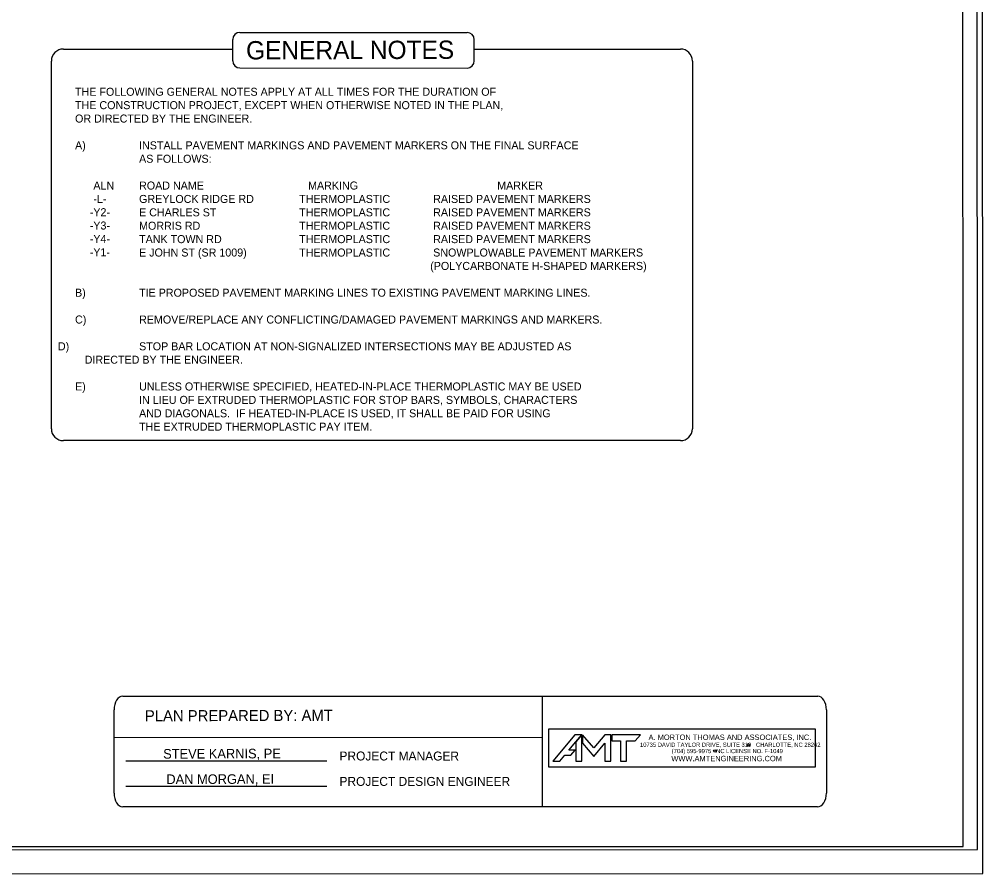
# Model space of a CAD drawing. Extents: x 2088685 to 2091711, y 751320 to 752417.
# Drawn here: x 2090071 to 2090874, y 751321 to 752034 of the extents above; entities that cross this region are included whole.
import ezdxf

# ---------------------------------------------------------------- set-up
doc = ezdxf.new("R2010")
doc.units = 0
for name, color, linetype in [('Default', 7, 'Continuous'), ('Prop Grid Mask', 7, 'Continuous'), ('Sheet Block Title CELL', 7, 'Continuous'), ('Sheet Plot Border Inside CELL', 7, 'Continuous'), ('Sheet Plot Border Outside CELL', 7, 'Continuous'), ('Sheet Title CELL', 7, 'Continuous')]:
    doc.layers.add(name, color=color, linetype=linetype)

msp = doc.modelspace()

# ---------------------------------------------------------------- linework, layer by layer
at = {"layer": 'Default'}
for p, q in [((2090157.69, 751469.16), (2090736.96, 751469.26)), ((2090507.46, 751376.87), (2090507.44, 751469.22)), ((2090150.52, 751388.35), (2090150.5, 751457.72)), ((2090744.15, 751457.77), (2090744.18, 751388.41)), ((2090150.49, 751434.81), (2090507.45, 751434.96)), ((2090160.34, 751415.41), (2090327.71, 751415.33)), ((2090160.33, 751394.22), (2090327.7, 751394.13)), ((2090736.86, 751376.91), (2090157.72, 751376.81))]:
    msp.add_line(p, q, dxfattribs=at)
for centre, major_axis, start_param, end_param in [((2090157.7, 751457.72), (0.01, 11.49), 0.000702, 1.571498), ((2090736.96, 751457.77), (0.01, 11.49), 4.713091, 6.283887), ((2090157.72, 751388.36), (-0.01, -11.49), 4.713091, 6.283887), ((2090736.98, 751388.4), (-0.01, -11.49), 6.268607, 7.854684)]:
    msp.add_ellipse(centre, major_axis=major_axis, ratio=0.62659, start_param=start_param, end_param=end_param, dxfattribs=at)
at = {"layer": 'Prop Grid Mask'}
msp.add_lwpolyline([(2090512.93, 751442.03), (2090734.97, 751442.03), (2090734.97, 751410.08), (2090512.93, 751410.08)], close=True, dxfattribs=at)
at = {"layer": 'Sheet Block Title CELL'}
for points in [[(2090858, 752393.6), (2089358.33, 752393.49), (2089358.41, 751343.72), (2090858.08, 751343.83)], [(2090512.93, 751442.03), (2090734.97, 751442.03), (2090734.97, 751410.08), (2090512.93, 751410.08)]]:
    msp.add_lwpolyline(points, close=True, dxfattribs=at)
for points in [[(2090535.36, 751431.17), (2090540.39, 751437.07), (2090534.51, 751437.07), (2090516.28, 751415.12), (2090521.98, 751415.12), (2090526.07, 751420.05), (2090531.29, 751420.05), (2090534.87, 751424.2), (2090529.48, 751424.2), (2090535.36, 751431.17)], [(2090540.39, 751415.12), (2090540.39, 751437.07), (2090535.36, 751431.17), (2090535.36, 751415.12), (2090540.39, 751415.12)], [(2090550.26, 751418.99), (2090559.59, 751430.1), (2090559.59, 751415.12), (2090564.62, 751415.12), (2090564.62, 751437.07), (2090559.59, 751437.07), (2090550.26, 751426.12), (2090541.04, 751437.07), (2090541.04, 751430.08), (2090550.26, 751418.99)], [(2090577.65, 751415.12), (2090577.65, 751432.04), (2090584.95, 751432.04), (2090589.15, 751437.07), (2090565.27, 751437.07), (2090565.27, 751432.04), (2090572.62, 751432.04), (2090572.62, 751415.12), (2090577.65, 751415.12)]]:
    msp.add_lwpolyline(points, dxfattribs=at)
for centre in [(2090679.16, 751428.6), (2090651.24, 751423.37)]:
    msp.add_circle(centre, 1, dxfattribs=at)
at = {"layer": 'Sheet Plot Border Inside CELL'}
msp.add_lwpolyline([(2090869.93, 752396.91), (2089204.86, 752396.79), (2089204.94, 751341.13), (2090870.01, 751341.25)], close=True, dxfattribs=at)
at = {"layer": 'Sheet Plot Border Outside CELL'}
msp.add_lwpolyline([(2090874.42, 752416.91), (2089191.88, 752416.79), (2089191.96, 751321.13), (2090874.5, 751321.25)], close=True, dxfattribs=at)
at = {"layer": 'Sheet Title CELL'}
for p, q in [((2090249.34, 751999.06), (2090249.35, 752016.69)), ((2090450.74, 751998.96), (2090450.74, 752016.59))]:
    msp.add_line(p, q, dxfattribs=at)
for points in [[(2090255.35, 752022.69), (2090444.75, 752022.6)], [(2090108.24, 752008.81), (2090249.34, 752008.81)], [(2090450.74, 752008.81), (2090622.48, 752008.81)], [(2090098.24, 751692.25), (2090098.24, 751998.81)], [(2090632.48, 751998.81), (2090632.48, 751692.25)], [(2090255.33, 751993.05), (2090444.73, 751992.97)], [(2090622.48, 751682.25), (2090108.24, 751682.25)]]:
    msp.add_lwpolyline(points, dxfattribs=at)
for centre, radius, start, end in [((2090255.35, 752016.69), 6, 89.97341, 179.97341), ((2090444.74, 752016.6), 6, 359.97341, 89.97341), ((2090108.24, 751998.81), 10, 90, 180), ((2090622.48, 751998.81), 10, 0, 90), ((2090255.34, 751999.05), 6, 179.97341, 269.97341), ((2090444.74, 751998.97), 6, 269.97341, 359.97341), ((2090108.24, 751692.25), 10, 180, 270), ((2090622.48, 751692.25), 10, 270, 0)]:
    msp.add_arc(centre, radius, start, end, dxfattribs=at)

# ---------------------------------------------------------------- texts
at = {"layer": 'Default'}
for s, height, rotation, p in [('GENERAL NOTES', 15.2572, 0.15565, (2090260.52, 752000.16)), ('ALN', 6.671, 359.97341, (2090133.24, 751891.66)), ('-L-', 6.671, 359.97341, (2090133.24, 751880.54)), ('-Y2-', 6.671, 359.97341, (2090130.24, 751869.42)), ('-Y3-', 6.671, 359.97341, (2090130.23, 751858.31)), ('-Y4-', 6.671, 359.97341, (2090130.23, 751847.19)), ('-Y1-', 6.671, 359.97341, (2090130.22, 751836.07)), ('PLAN PREPARED BY: AMT', 9.2466, 0.15565, (2090176.18, 751448.2)), ('STEVE KARNIS, PE', 8, 0.15565, (2090191.41, 751417.11)), ('PROJECT MANAGER', 7.4502, 359.97341, (2090338.37, 751415.59)), ('DAN MORGAN, EI', 8, 0.15565, (2090194.09, 751395.92)), ('PROJECT DESIGN ENGINEER', 7.4502, 359.97341, (2090338.36, 751394.41))]:
    msp.add_text(s, height=height, rotation=rotation, dxfattribs=at).set_placement(p)
at = {"layer": 'Sheet Block Title CELL'}
for s, height, p in [('A. MORTON THOMAS AND ASSOCIATES, INC.', 4.5, (2090595.94, 751432.68)), ('10735 DAVID TAYLOR DRIVE, SUITE 310   CHARLOTTE, NC 28262', 3.5, (2090588.84, 751426.93)), ('WWW.AMTENGINEERING.COM', 4.5, (2090614.96, 751414.93)), ('(704) 595-9975   NC LICENSE NO. F-1049', 3.5, (2090615.23, 751421.68))]:
    msp.add_text(s, height=height, rotation=359.99952, dxfattribs=at).set_placement(p)
at = {"layer": 'Sheet Title CELL'}
for s, height, p in [('THE FOLLOWING GENERAL NOTES APPLY AT ALL TIMES FOR THE DURATION OF', 6.6709, (2090117.98, 751969.85)), ('THE CONSTRUCTION PROJECT, EXCEPT WHEN OTHERWISE NOTED IN THE PLAN,', 6.6709, (2090117.98, 751958.68)), ('OR DIRECTED BY THE ENGINEER.', 6.6709, (2090117.98, 751947.51)), ('A)', 6.671, (2090117.98, 751925.17)), ('INSTALL PAVEMENT MARKINGS AND PAVEMENT MARKERS ON THE FINAL SURFACE', 6.6709, (2090171.34, 751925.17)), ('AS FOLLOWS:', 6.6709, (2090171.34, 751913.99)), ('ROAD NAME', 6.671, (2090171.34, 751891.65)), ('   MARKING', 6.671, (2090304.76, 751891.65)), ('  MARKER', 6.671, (2090464.86, 751891.65)), ('GREYLOCK RIDGE RD', 6.6709, (2090171.34, 751880.48)), ('THERMOPLASTIC', 6.6709, (2090304.76, 751880.48)), ('  RAISED PAVEMENT MARKERS', 6.6709, (2090411.5, 751880.48)), ('E CHARLES ST', 6.6709, (2090171.34, 751869.31)), ('THERMOPLASTIC', 6.6709, (2090304.76, 751869.31)), ('  RAISED PAVEMENT MARKERS', 6.6709, (2090411.5, 751869.31)), ('MORRIS RD', 6.671, (2090171.34, 751858.14)), ('THERMOPLASTIC', 6.6709, (2090304.76, 751858.14)), ('  RAISED PAVEMENT MARKERS', 6.6709, (2090411.5, 751858.14)), ('TANK TOWN RD', 6.6709, (2090171.34, 751846.97)), ('THERMOPLASTIC', 6.6709, (2090304.76, 751846.97)), ('  RAISED PAVEMENT MARKERS', 6.6709, (2090411.5, 751846.97)), ('E JOHN ST (SR 1009)', 6.6709, (2090171.34, 751835.8)), ('THERMOPLASTIC', 6.6709, (2090304.76, 751835.8)), ('  SNOWPLOWABLE PAVEMENT MARKERS', 6.6709, (2090411.5, 751835.8)), (' (POLYCARBONATE H-SHAPED MARKERS)', 6.6709, (2090411.5, 751824.63)), ('B)', 6.671, (2090117.98, 751802.29)), ('TIE PROPOSED PAVEMENT MARKING LINES TO EXISTING PAVEMENT MARKING LINES.', 6.6709, (2090171.34, 751802.29)), ('C)', 6.671, (2090117.98, 751779.94)), ('REMOVE/REPLACE ANY CONFLICTING/DAMAGED PAVEMENT MARKINGS AND MARKERS.', 6.6709, (2090171.34, 751779.94)), ('     D)  ', 6.671, (2090091.29, 751757.6)), ('STOP BAR LOCATION AT NON-SIGNALIZED INTERSECTIONS MAY BE ADJUSTED AS ', 6.6709, (2090171.34, 751757.6)), ('              DIRECTED BY THE ENGINEER.', 6.6709, (2090091.29, 751746.43)), ('E)  ', 6.671, (2090117.98, 751724.09)), ('UNLESS OTHERWISE SPECIFIED, HEATED-IN-PLACE THERMOPLASTIC MAY BE USED', 6.6709, (2090171.34, 751724.09)), ('IN LIEU OF EXTRUDED THERMOPLASTIC FOR STOP BARS, SYMBOLS, CHARACTERS ', 6.6709, (2090171.34, 751712.92)), ('AND DIAGONALS.  IF HEATED-IN-PLACE IS USED, IT SHALL BE PAID FOR USING ', 6.6709, (2090171.34, 751701.75)), ('THE EXTRUDED THERMOPLASTIC PAY ITEM.', 6.6709, (2090171.34, 751690.58))]:
    msp.add_text(s, height=height, dxfattribs=at).set_placement(p)

doc.saveas('drawing.dxf')
